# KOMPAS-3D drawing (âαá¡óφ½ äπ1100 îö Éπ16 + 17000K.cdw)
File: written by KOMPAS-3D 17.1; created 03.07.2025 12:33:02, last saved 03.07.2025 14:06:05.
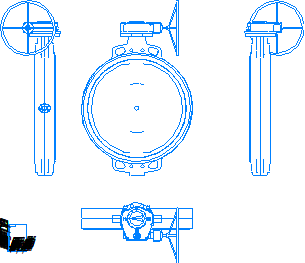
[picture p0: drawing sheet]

Sheet 1: A4, portrait

Title block, sheet 1: sheets: 1; sheet format: A4; stored path: \\adlc.lan\data\АДЛ_ПКД\3D-модели\ADL production\Дисковые поворотные затворы ГРАНВЭЛ\межфланцевый с китайским редуктором Ру16\KOMPAS 2D\Гранвэл Ду1100 МФ Ру16 + 17000K.cdw

Views: Проекционный вид 2, Проекционный вид 3, Проекционный вид 4
Referenced files in \\adlc.lan\data\АДЛ_ПКД\3D-модели\ADL production\Дисковые поворотные затворы ГРАНВЭЛ\межфланцевый с китайским редуктором Ру16\KOMPAS 3D\: Гранвэл Ду1100 МФ Ру16 + 17000K.m3d
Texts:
  Andrey
  АДЛ
Dimensions and other numbers on the sheet: 1:1; 1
